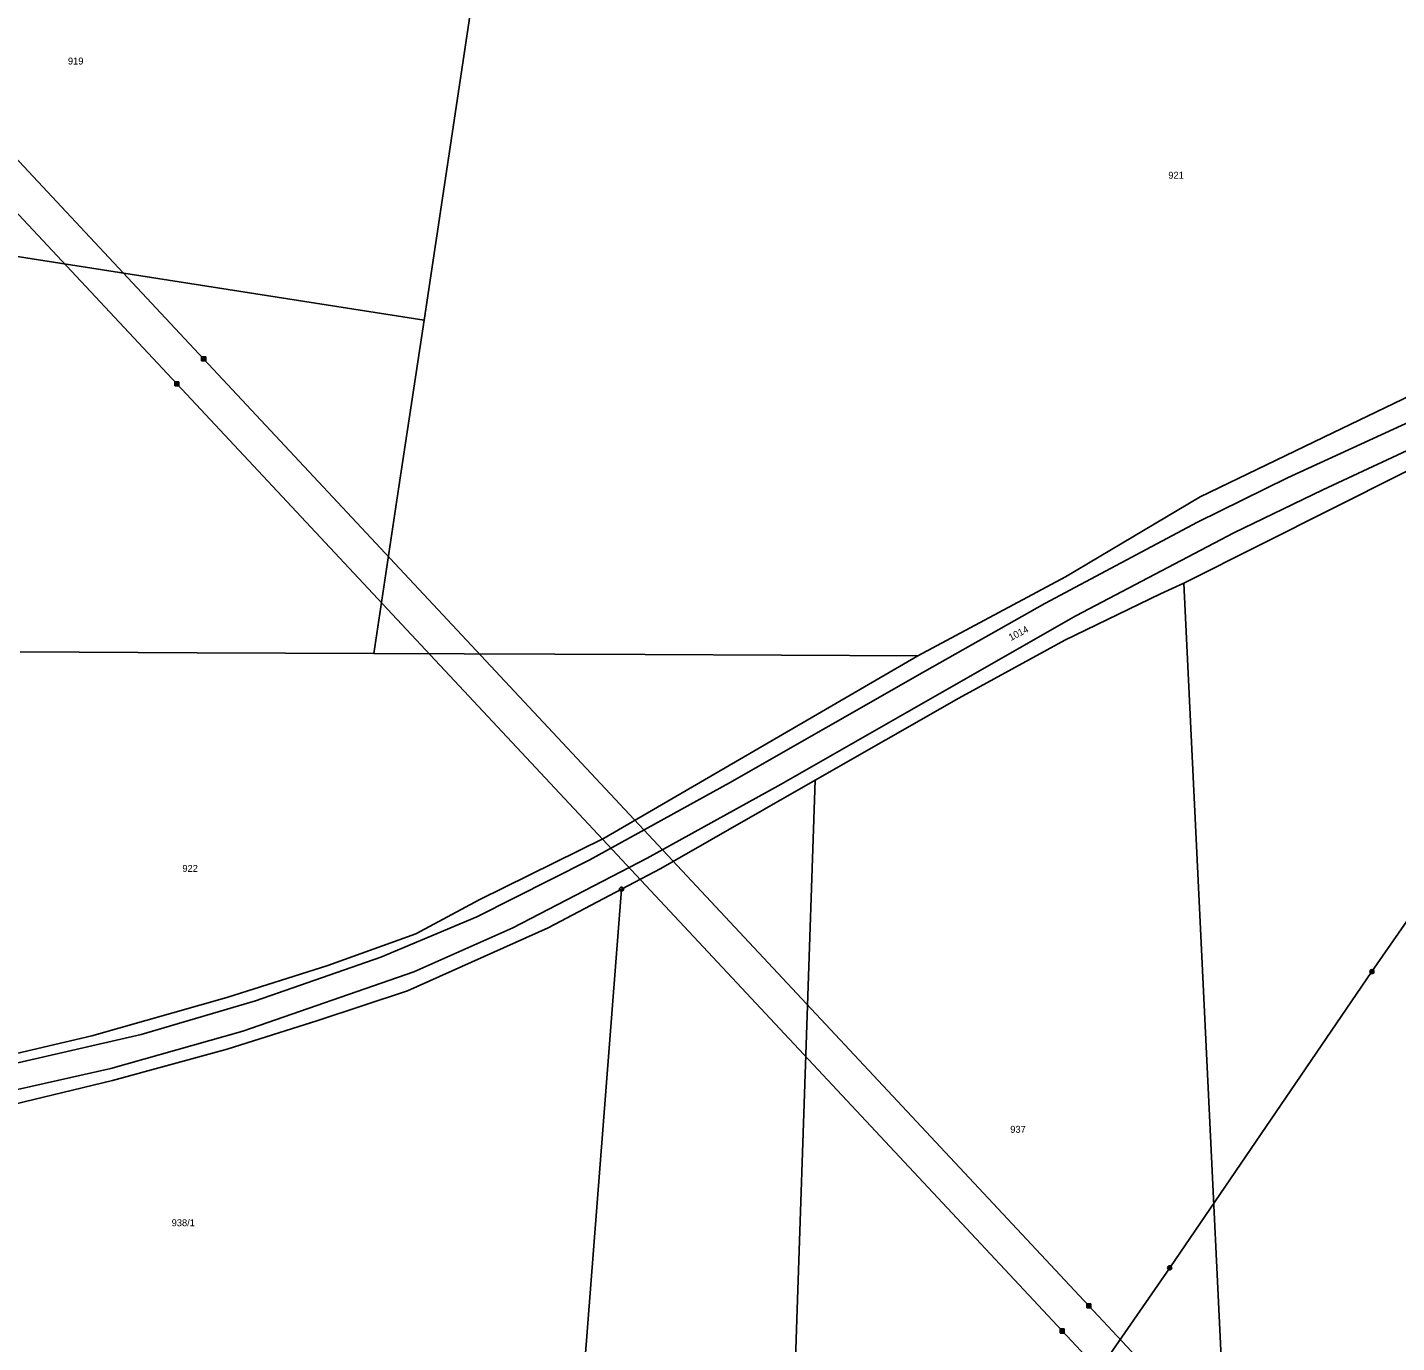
# Model space of a CAD drawing. Extents: x -738131 to -734179, y -1033447 to -1030078.
# Drawn here: x -735564.5 to -735229.5, y -1031681.6 to -1031360 of the extents above; entities that cross this region are included whole.
import ezdxf

# ---------------------------------------------------------------- set-up
doc = ezdxf.new("R2010")
doc.units = 0
for name, color, linetype in [('Vrstva 1', 7, 'Continuous'), ('Vrstva 2', 7, 'Continuous'), ('Vrstva 4', 7, 'Continuous'), ('Vrstva 6', 7, 'Continuous'), ('Vrstva 8', 7, 'Continuous')]:
    doc.layers.add(name, color=color, linetype=linetype)

msp = doc.modelspace()

# ---------------------------------------------------------------- linework, layer by layer
at = {"layer": 'Vrstva 1'}
for points in [[(-735455.78, -1031354.03), (-735467.44, -1031431.63)], [(-735611.16, -1031409.08), (-735563.25, -1031416.61)], [(-735563.25, -1031416.61), (-735515.35, -1031424.12)], [(-735515.35, -1031424.12), (-735467.44, -1031431.63)], [(-735467.44, -1031431.63), (-735473.58, -1031472.37)], [(-735219.56, -1031446.85), (-735245.15, -1031459.13)], [(-735245.15, -1031459.13), (-735277.57, -1031474.77)], [(-735262.74, -1031486.45), (-735210.65, -1031460.28)], [(-735473.58, -1031472.37), (-735479.68, -1031513.1)], [(-735277.57, -1031474.77), (-735310.56, -1031494.39)], [(-735281.57, -1031495.9), (-735262.74, -1031486.45)], [(-735310.56, -1031494.39), (-735346.65, -1031513.69)], [(-735287.27, -1031498.51), (-735281.57, -1031495.9)], [(-735281.57, -1031495.9), (-735276.42, -1031602.42)], [(-735310.72, -1031509.87), (-735287.27, -1031498.51)], [(-735336.63, -1031524), (-735310.72, -1031509.87)], [(-735566.19, -1031512.72), (-735522.93, -1031512.92)], [(-735522.93, -1031512.92), (-735479.68, -1031513.1)], [(-735413.37, -1031513.37), (-735479.68, -1031513.1)], [(-735346.65, -1031513.69), (-735413.37, -1031513.37)], [(-735346.65, -1031513.69), (-735423.39, -1031558.28)], [(-735371.79, -1031544.03), (-735336.63, -1031524)], [(-735409.53, -1031565.65), (-735371.79, -1031544.03)], [(-735371.79, -1031544.03), (-735376.16, -1031673.49)], [(-735423.39, -1031558.28), (-735453.98, -1031573.36)], [(-735419.14, -1031570.73), (-735409.53, -1031565.65)], [(-735480.16, -1031700.61), (-735429.68, -1031706.26), (-735419.14, -1031570.73)], [(-735453.98, -1031573.36), (-735469.43, -1031581.68)], [(-735437.04, -1031580.2), (-735419.14, -1031570.73)], [(-735471.48, -1031595.59), (-735437.04, -1031580.2)], [(-735469.43, -1031581.68), (-735490.97, -1031589.39)], [(-735490.97, -1031589.39), (-735515.64, -1031597.24)], [(-735515.64, -1031597.24), (-735548.68, -1031606.54)], [(-735493.44, -1031602.84), (-735471.48, -1031595.59)], [(-735515.61, -1031609.8), (-735493.44, -1031602.84)], [(-735276.42, -1031602.42), (-735271.28, -1031708.87)], [(-735548.68, -1031606.54), (-735569.9, -1031611.58)], [(-735543.63, -1031617.53), (-735515.61, -1031609.8)], [(-735587.29, -1031628.05), (-735543.63, -1031617.53)], [(-735376.16, -1031673.49), (-735380.53, -1031802.94)]]:
    msp.add_lwpolyline(points, dxfattribs=at)
at = {"layer": 'Vrstva 4'}
for points in [[(-735256.23, -1031470.16), (-735225.35, -1031455.95)], [(-735219.6, -1031460.07), (-735247.59, -1031473.05)], [(-735278.23, -1031480.98), (-735256.23, -1031470.16)], [(-735247.59, -1031473.05), (-735269.34, -1031483.57)], [(-735315.6, -1031500.9), (-735278.23, -1031480.98)], [(-735269.34, -1031483.57), (-735308.04, -1031503.86)], [(-735345.05, -1031517.48), (-735315.6, -1031500.9)], [(-735308.04, -1031503.86), (-735341.3, -1031522.85)], [(-735392.75, -1031544.71), (-735345.05, -1031517.48)], [(-735341.3, -1031522.85), (-735380.09, -1031545.07)], [(-735427.03, -1031563.61), (-735392.75, -1031544.71)], [(-735380.09, -1031545.07), (-735412.82, -1031563.17)], [(-735454.52, -1031577.52), (-735427.03, -1031563.61)], [(-735412.82, -1031563.17), (-735445.7, -1031580.18)], [(-735478.01, -1031587.36), (-735454.52, -1031577.52)], [(-735445.7, -1031580.18), (-735469.9, -1031590.94)], [(-735508.62, -1031597.99), (-735478.01, -1031587.36)], [(-735469.9, -1031590.94), (-735511.74, -1031605.4)], [(-735536.65, -1031606.22), (-735508.62, -1031597.99)], [(-735583.91, -1031617.13), (-735536.65, -1031606.22)], [(-735511.74, -1031605.4), (-735544.05, -1031614.59)], [(-735544.05, -1031614.59), (-735583.23, -1031623.4)]]:
    msp.add_lwpolyline(points, dxfattribs=at)
at = {"layer": 'Vrstva 6'}
for p, q in [((-735521.84, -1031440.52), (-735520.84, -1031440.52)), ((-735521.84, -1031441.52), (-735521.84, -1031440.52)), ((-735521.84, -1031440.72), (-735520.84, -1031440.72)), ((-735521.84, -1031440.92), (-735520.84, -1031440.92)), ((-735521.84, -1031441.12), (-735520.84, -1031441.12)), ((-735521.84, -1031441.32), (-735520.84, -1031441.32)), ((-735521.84, -1031441.52), (-735520.84, -1031441.52)), ((-735521.64, -1031441.52), (-735521.64, -1031440.52)), ((-735521.44, -1031441.52), (-735521.44, -1031440.52)), ((-735521.24, -1031441.52), (-735521.24, -1031440.52)), ((-735521.04, -1031441.52), (-735521.04, -1031440.52)), ((-735520.84, -1031441.52), (-735520.84, -1031440.52)), ((-735528.43, -1031446.67), (-735527.43, -1031446.67)), ((-735528.43, -1031447.67), (-735528.43, -1031446.67)), ((-735528.43, -1031446.87), (-735527.43, -1031446.87)), ((-735528.43, -1031447.07), (-735527.43, -1031447.07)), ((-735528.43, -1031447.27), (-735527.43, -1031447.27)), ((-735528.43, -1031447.47), (-735527.43, -1031447.47)), ((-735528.43, -1031447.67), (-735527.43, -1031447.67)), ((-735528.23, -1031447.67), (-735528.23, -1031446.67)), ((-735528.03, -1031447.67), (-735528.03, -1031446.67)), ((-735527.83, -1031447.67), (-735527.83, -1031446.67)), ((-735527.63, -1031447.67), (-735527.63, -1031446.67)), ((-735527.43, -1031447.67), (-735527.43, -1031446.67)), ((-735305.32, -1031672.11), (-735304.32, -1031672.11)), ((-735305.32, -1031673.11), (-735305.32, -1031672.11)), ((-735305.32, -1031672.31), (-735304.32, -1031672.31)), ((-735305.32, -1031672.51), (-735304.32, -1031672.51)), ((-735305.32, -1031672.71), (-735304.32, -1031672.71)), ((-735305.32, -1031672.91), (-735304.32, -1031672.91)), ((-735305.32, -1031673.11), (-735304.32, -1031673.11)), ((-735305.12, -1031673.11), (-735305.12, -1031672.11)), ((-735304.92, -1031673.11), (-735304.92, -1031672.11)), ((-735304.72, -1031673.11), (-735304.72, -1031672.11)), ((-735304.52, -1031673.11), (-735304.52, -1031672.11)), ((-735304.32, -1031673.11), (-735304.32, -1031672.11)), ((-735311.88, -1031678.25), (-735310.88, -1031678.25)), ((-735311.88, -1031679.25), (-735311.88, -1031678.25)), ((-735311.88, -1031678.45), (-735310.88, -1031678.45)), ((-735311.88, -1031678.65), (-735310.88, -1031678.65)), ((-735311.88, -1031678.85), (-735310.88, -1031678.85)), ((-735311.88, -1031679.05), (-735310.88, -1031679.05)), ((-735311.88, -1031679.25), (-735310.88, -1031679.25)), ((-735311.68, -1031679.25), (-735311.68, -1031678.25)), ((-735311.48, -1031679.25), (-735311.48, -1031678.25)), ((-735311.28, -1031679.25), (-735311.28, -1031678.25)), ((-735311.08, -1031679.25), (-735311.08, -1031678.25)), ((-735310.88, -1031679.25), (-735310.88, -1031678.25))]:
    msp.add_line(p, q, dxfattribs=at)
for points in [[(-735712.32, -1031236.74), (-735521.34, -1031441.02)], [(-735718.9, -1031242.89), (-735527.93, -1031447.17)], [(-735521.34, -1031441.02), (-735304.82, -1031672.61)], [(-735527.93, -1031447.17), (-735311.38, -1031678.75)], [(-735235.58, -1031590.87), (-735181.59, -1031513.18)], [(-735285.05, -1031663.31), (-735235.58, -1031590.87)], [(-735312.88, -1031703.54), (-735285.05, -1031663.31)], [(-735304.82, -1031672.61), (-735085.11, -1031907.68)], [(-735311.38, -1031678.75), (-735091.67, -1031913.81)]]:
    msp.add_lwpolyline(points, dxfattribs=at)
for centre, radius in [((-735235.58, -1031590.87), 0.5), ((-735235.58, -1031590.87), 0.4), ((-735235.58, -1031590.87), 0.3), ((-735235.58, -1031590.87), 0.2), ((-735235.58, -1031590.87), 0.1), ((-735285.05, -1031663.31), 0.5), ((-735285.05, -1031663.31), 0.4), ((-735285.05, -1031663.31), 0.3), ((-735285.05, -1031663.31), 0.2), ((-735285.05, -1031663.31), 0.1)]:
    msp.add_circle(centre, radius, dxfattribs=at)
at = {"layer": 'Vrstva 8'}
for radius in [0.5, 0.0303]:
    msp.add_circle((-735419.14, -1031570.73), radius, dxfattribs=at)

# ---------------------------------------------------------------- texts
at = {"layer": 'Vrstva 2'}
for s, p in [('919', (-735554.54, -1031369.08)), ('921', (-735285.38, -1031397.01)), ('922', (-735526.55, -1031566.5)), ('937', (-735324.04, -1031630.29)), ('938/1', (-735529.17, -1031653.14))]:
    msp.add_text(s, height=1.7, dxfattribs=at).set_placement(p)
msp.add_text('1014', height=1.7, rotation=27.3874, dxfattribs=at).set_placement((-735323.9, -1031510.05))

doc.saveas('drawing.dxf')
